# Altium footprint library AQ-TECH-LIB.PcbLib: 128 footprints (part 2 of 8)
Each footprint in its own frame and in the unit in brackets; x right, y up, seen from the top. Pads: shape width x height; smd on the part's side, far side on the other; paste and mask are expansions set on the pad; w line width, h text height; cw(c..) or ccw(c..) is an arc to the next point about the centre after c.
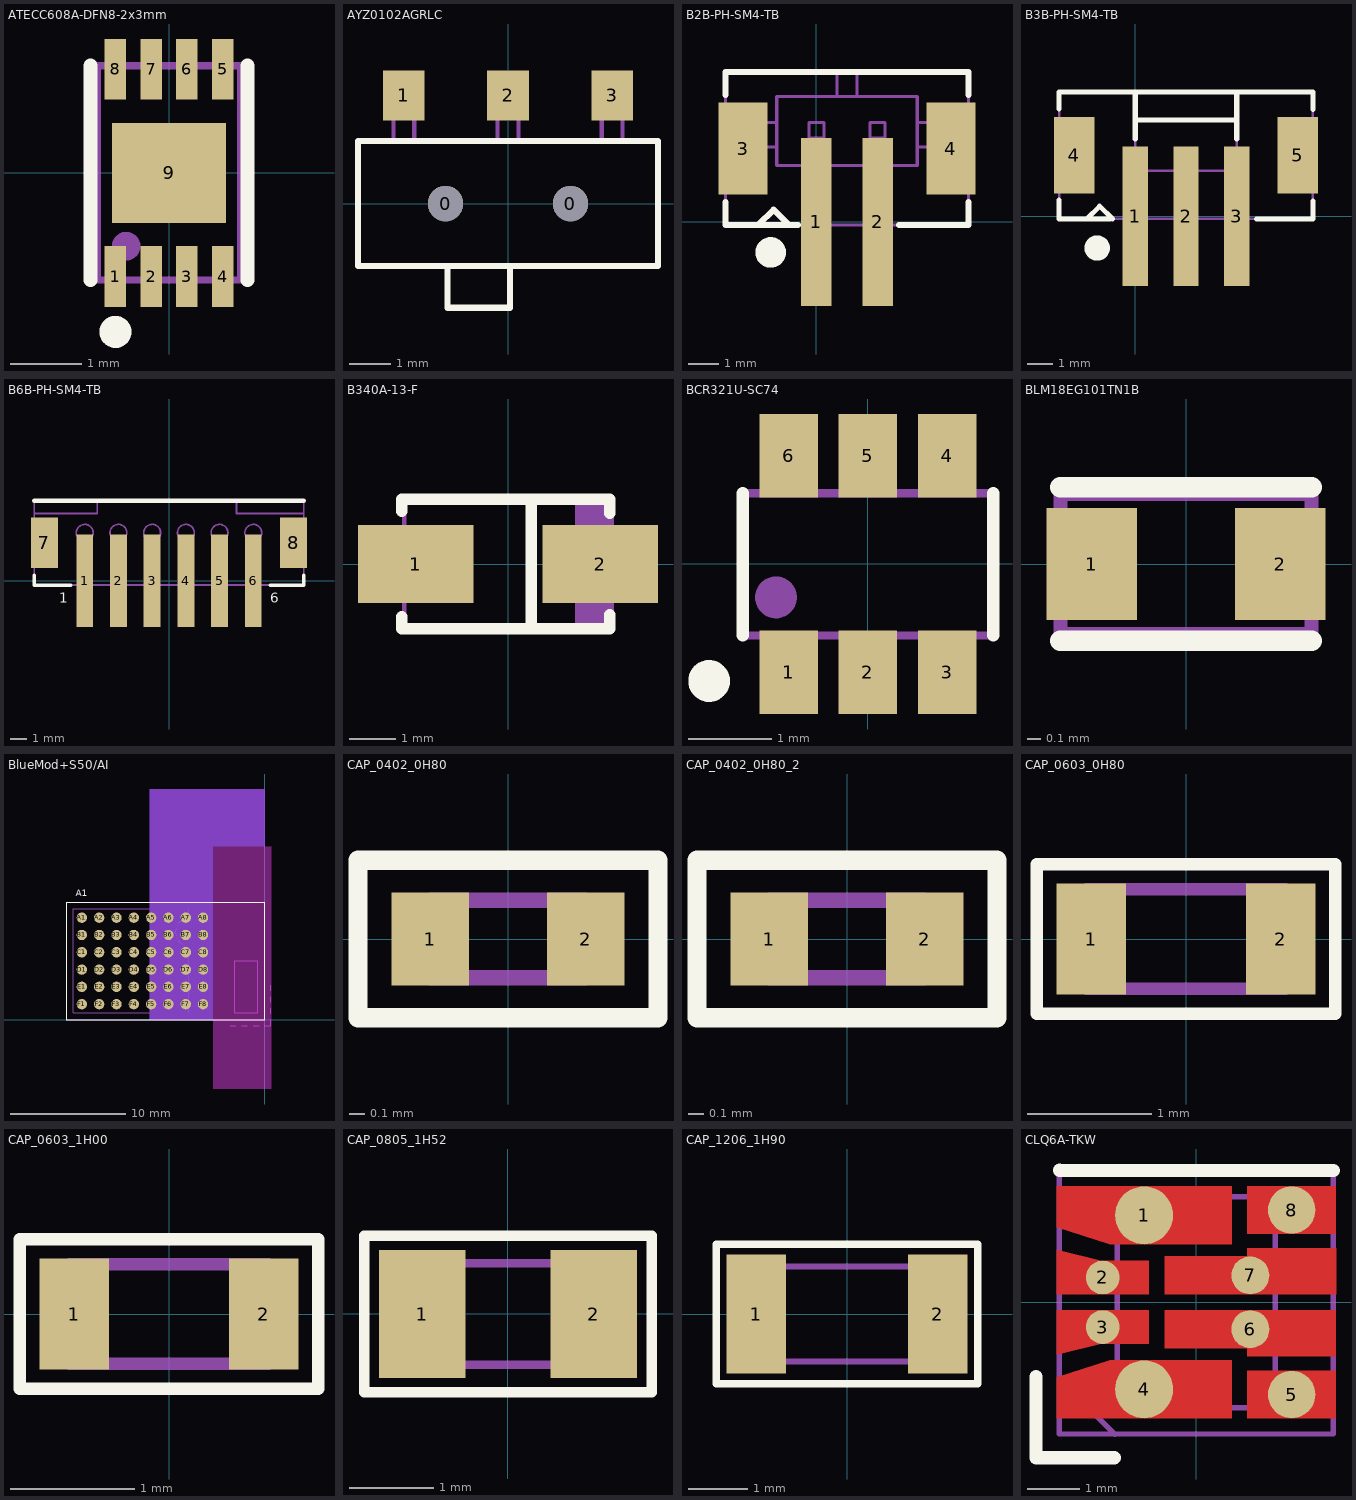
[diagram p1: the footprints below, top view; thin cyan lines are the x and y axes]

## ATECC608A-DFN8-2x3mm [mm]
height 0.6
pads (9):
  rect 0.3x0.85 smd mask+0.05: 1(-0.75,-1.45) 2(-0.25,-1.45) 3(0.25,-1.45) 4(0.75,-1.45) 5(0.75,1.45) 6(0.25,1.45) 7(-0.25,1.45) 8(-0.75,1.45)
  rect 1.6x1.4 smd: 9(0,0)
Top Overlay:
  circle w0.25: c-0.75,-2.225 r0.1
  lines w0.2: -1.1,-1.5 -1.1,1.5 ; 1.1,-1.5 1.1,1.5
Mechanical 3:
  circle w0.2: c-0.6,-1.025 r0.1
  lines w0.1: -1,-1.5 1,-1.5 1,1.5 -1,1.5 -1,-1.5
  text ".Designator" at -1.35,-1.25 h0.84
3D body: height 0.61, standoff 0, extent -0.849,-1.274 -0.351,-0.775
3D body: height 0.6, standoff 0, extent -1,-1.5 1,1.5

## AYZ0102AGRLC [mm]
height 1.5
pads (5):
  round 0.85 hole 0.85 paste+0 mask+0.05: 0(-1.5,0) 0(1.5,0)
  rect 1x1.2 smd paste+0 mask+0.05: 1(-2.5,2.6) 2(0,2.6) 3(2.5,2.6)
Top Overlay:
  lines w0.15: -3.6,-1.5 3.6,-1.5 3.6,1.5 -3.6,1.5 -3.6,-1.5 ; -1.45,-2.5 0.05,-2.5 0.05,-1.5 -1.45,-1.5 -1.45,-2.5
Mechanical 3:
  lines w0.1: -3.6,-1.5 -3.6,1.5 3.6,1.5 3.6,-1.5 -3.6,-1.5 ; -2.75,1.5 -2.75,2.8 -2.25,2.8 -2.25,1.5 -2.75,1.5 ; -1.45,-2.5 0.05,-2.5 0.05,-1.5 -1.45,-1.5 -1.45,-2.5 ; -0.25,1.5 0.25,1.5 0.25,2.8 -0.25,2.8 -0.25,1.5 ; 2.25,1.5 2.75,1.5 2.75,2.8 2.25,2.8 2.25,1.5
  text ".Designator" at -0.04,-0.04 h0.84
3D body: height 0.2, standoff 0, extent 2.25,1.5 2.75,2.8
3D body: height 0.2, standoff 0, extent -0.25,1.5 0.25,2.8
3D body: height 0.2, standoff 0, extent -2.75,1.5 -2.25,2.8
3D body: height 1.3, standoff 0.8, extent -1.45,-2.5 0.05,-1.5
3D body: height 1.5, standoff 0, extent -3.6,-1.5 3.6,1.5

## B2B-PH-SM4-TB [mm]
height 6.6
pads (4):
  rect 1x5.5 smd paste+0 mask+0.1: 1(0,0) 2(2,0)
  rect 1.6x3.02 smd paste+0 mask+0.1: 3(-2.4,2.4) 4(4.4,2.4)
Top Overlay:
  circle w0.5: c-1.5,-1 r0.25
  lines w0.2: -2.975,0.65 -2.975,-0.1 -0.6,-0.1 ; -2.975,4.15 -2.975,4.9 4.975,4.9 4.975,4.15 ; -1.9,-0.1 -1.4,0.4 -0.9,-0.1 ; 2.7,-0.1 4.975,-0.1 4.975,0.65
Mechanical 3:
  lines w0.1: -2.925,1.3 -2.925,3.5 ; -2.325,1.3 -2.325,3.5 ; -1.9,-0.1 -1.4,0.4 -0.9,-0.1 ; -0.25,-0.1 -0.25,-2.1 0.25,-2.1 0.25,-0.1 ; 1.75,-0.1 1.75,-2.1 2.25,-2.1 2.25,-0.1 ; 4.325,1.3 4.325,3.5 4.925,3.5 4.925,1.3 ; -2.075,2.45 -2.075,1.3 -2.975,1.3 -2.975,-0.1 4.975,-0.1 4.975,1.3 4.075,1.3 4.075,2.45 ; -2.075,2.45 -1.3,2.45 ; -2.075,2.45 -2.075,3.25 ; -2.075,3.25 -2.075,3.5 -2.975,3.5 -2.975,4.9 0.675,4.9 ; -2.075,3.25 -1.3,3.25 ; -1.3,2.45 -1.3,1.85 3.3,1.85 3.3,2.45 ; -1.3,2.45 -1.3,3.25 ; -1.3,3.25 -1.3,4.1 0.675,4.1 ; 0.675,4.1 1.325,4.1 ; 0.675,4.1 0.675,4.9 ; 0.675,4.9 1.325,4.9 ; 1.325,4.1 1.325,4.9 ; 1.325,4.1 3.3,4.1 3.3,3.25 ; 1.325,4.9 4.975,4.9 4.975,3.5 4.075,3.5 4.075,3.25 ; 3.3,2.45 4.075,2.45 ; 3.3,2.45 3.3,3.25 ; 3.3,3.25 4.075,3.25 ; 4.075,2.45 4.075,3.25 ; -0.25,2.75 -0.25,3.25 0.25,3.25 0.25,2.75 -0.25,2.75 ; 1.75,2.75 1.75,3.25 2.25,3.25 2.25,2.75 1.75,2.75
  text "2" at 2.5,0.2 h0.84
  text "1" at -0.9,0.3 h0.84
  text ".Designator" at -3.6,1.844 h0.84
3D body "B2B-PH-SM4-TB(LF)(SN)--3DModel-STEP-56544.STEP": height 6.71, standoff -0.04, extent -2.975,-2.1 4.975,4.9

## B3B-PH-SM4-TB [mm]
height 6.6
pads (5):
  rect 1x5.5 smd paste+0 mask+0.1: 1(0,0) 2(2,0) 3(4,0)
  rect 1.6x3.02 smd paste+0 mask+0.1: 4(-2.4,2.4) 5(6.4,2.4)
Top Overlay:
  circle w0.5: c-1.5,-1.25 r0.25
  lines w0.2: -3,0.647 -3,-0.1 -2.6,-0.1 -1.8,-0.1 -1,-0.1 ; -3,4.234 -3,4.9 7,4.9 7,4.205 ; -2,4.9 4,4.9 ; -1.9,-0.1 -1.4,0.4 -0.9,-0.1 ; 0,3.041 0,4.8 ; 0,4.9 0,3.8 4,3.8 4,4.9 ; 4,3.051 4,4.9 ; 4.778,-0.1 7,-0.1 7,0.608
Mechanical 3:
  lines w0.1: -2,4.9 4,4.9 ; -1.9,-0.1 -1.4,0.4 -0.9,-0.1 ; 0,-0.1 0,1.8 4,1.8 4,-0.1 ; 0,-0.1 4,-0.1 ; 0,-0.1 0,4.9 ; 0,-0.1 4,-0.1 ; 0,4.9 0,3.8 4,3.8 4,4.9 ; 0,4.9 4,4.9 ; 4,-0.1 4,4.9 ; -3,-0.1 -3,4.9 7,4.9 7,-0.1 -3,-0.1
  text ".Designator" at -3.9,1.6 h0.84
  text "1" at -0.9,0.2 h0.84
  text "3" at 4.3,0.2 h0.84
3D body "B3B-PH-SM4-TB-LF--SN---3DModel-STEP-56544.STEP": height 6.71, standoff -0.04, extent -2.975,-2.1 6.975,4.9

## B6B-PH-SM4-TB [mm]
height 6.6
pads (8):
  rect 1x5.5 smd paste+0 mask+0.1: 1(-5,0) 2(-3,0) 3(-1,0) 4(1,0) 5(3,0) 6(5,0)
  rect 1.6x3 smd paste+0 mask+0.1: 7(-7.4,2.25) 8(7.4,2.25)
Top Overlay:
  lines w0.2: -8,0.35 -8,-0.25 -5.825,-0.25 ; 6,-0.25 8,-0.25 8,0.35
  lines w0.25: -8,4.75 8,4.75
  text "6" at 6,-1.5 h1
  text "1" at -6.5,-1.5 h1
Mechanical 3:
  circle w0.1: c5,2.85 r0.5
  circle w0.1: c3,2.85 r0.5
  circle w0.1: c1,2.85 r0.5
  circle w0.1: c-1,2.85 r0.5
  circle w0.1: c-3,2.85 r0.5
  circle w0.1: c-5,2.85 r0.5
  lines w0.1: -8,4 -4.25,4 -4.25,4.75 ; 4,4.75 4,4 8,4 ; -8,-0.25 -8,4.75 8,4.75 8,-0.25 -8,-0.25
  text "6" at 5,0.25 h1
  text "1" at -5,0.25 h1
  text ".Designator" at 0,0.5 h0.84
3D body "B6B-PH-SM4-TB(LF)(SN)--3DModel-STEP-56544.STEP": height 6.75, standoff 0, extent -7.975,-2.25 7.975,4.75

## B340A-13-F [mm]
height 2.4
pads (2):
  rect 2.5x1.7 smd paste+0 mask+0.1: 1(-2,0) 2(2,0)
Top Overlay:
  lines w0.25: -2.3,-1.143 -2.3,-1.4 2.2,-1.4 2.2,-1.1 ; -2.3,1.143 -2.3,1.4 2.2,1.4 2.2,1.1 ; 0.5,-1.3 0.5,1.4
Mechanical 3:
  region: 1.5,-1.39 2.24,-1.39 2.24,1.4 1.5,1.4
  lines w0.1: 1.5,-1.395 1.5,1.395 ; -2.64,-0.735 -2.64,0.735 -2.25,0.735 -2.25,-0.735 -2.64,-0.735 ; -2.25,-1.395 -2.25,1.395 2.25,1.395 2.25,-1.395 -2.25,-1.395 ; 2.25,-0.735 2.64,-0.735 2.64,0.735 2.25,0.735 2.25,-0.735
  text ".Designator" at -2,0 h0.84
3D body "DO214AC(refusion).stp": height 2.4, standoff 0, extent -2.6,-1.3 2.6,1.3

## BCR321U-SC74 [mm]
height 1.1
pads (6):
  rect 0.7x1 smd paste+0 mask+0.05: 1(-0.95,-1.295) 2(0,-1.295) 3(0.95,-1.295) 4(0.95,1.295) 5(0,1.295) 6(-0.95,1.295)
Top Overlay:
  circle w0.3: c-1.9,-1.4 r0.1
  lines w0.15: -1.5,-0.855 -1.5,0.845 ; 1.5,-0.855 1.5,0.845
Mechanical 3:
  circle w0.3: c-1.1,-0.4 r0.1
  lines w0.1: -1.5,-0.855 -1.5,0.845 1.5,0.845 1.5,-0.855 -1.5,-0.855
  text ".Designator" at 1.25,0.525 h1
3D body: height 1.1, standoff 0, extent -1.5,-0.855 1.5,0.845
3D body: height 1.11, standoff 0, extent -1.349,-0.65 -0.851,-0.15

## BLM18EG101TN1B [mm]
height 0.65
pads (2):
  rect 0.65x0.8 smd: 1(-0.675,0) 2(0.675,0)
Top Overlay:
  lines w0.15: -0.9,-0.55 0.9,-0.55 ; -0.9,0.55 0.9,0.55
Mechanical 3:
  lines w0.1: -0.9,-0.5 -0.9,0.5 0.9,0.5 0.9,-0.5 -0.9,-0.5
  text "'.Designator'" at 0,0 h1
3D body: height 0.65, standoff 0, extent -0.9,-0.5 0.9,0.5

## BlueMod+S50/AI [mm]
height 3.05
pads (48):
  round 0.9 smd: A1(-15.85,8.85) A2(-14.35,8.85) A3(-12.85,8.85) A4(-11.35,8.85) A5(-9.85,8.85) A6(-8.35,8.85) A7(-6.85,8.85) A8(-5.35,8.85) B1(-15.85,7.35) B2(-14.35,7.35) B3(-12.85,7.35) B4(-11.35,7.35) B5(-9.85,7.35) B6(-8.35,7.35) B7(-6.85,7.35) B8(-5.35,7.35) C1(-15.85,5.85) C2(-14.35,5.85) C3(-12.85,5.85) C4(-11.35,5.85) C5(-9.85,5.85) C6(-8.35,5.85) C7(-6.85,5.85) C8(-5.35,5.85) D1(-15.85,4.35) D2(-14.35,4.35) D3(-12.85,4.35) D4(-11.35,4.35) D5(-9.85,4.35) D6(-8.35,4.35) D7(-6.85,4.35) D8(-5.35,4.35) E1(-15.85,2.85) E2(-14.35,2.85) E3(-12.85,2.85) E4(-11.35,2.85) E5(-9.85,2.85) E6(-8.35,2.85) E7(-6.85,2.85) E8(-5.35,2.85) F1(-15.85,1.35) F2(-14.35,1.35) F3(-12.85,1.35) F4(-11.35,1.35) F5(-9.85,1.35) F6(-8.35,1.35) F7(-6.85,1.35) F8(-5.35,1.35)
Top Layer keep-out:
  rectangle: -10,10 -4.5,15
  rectangle: -10,15 0,20
Bottom Layer keep-out:
  rectangle: -10,0 -4.5,20
  rectangle: -10,15 0,20
Top Overlay:
  lines w0.1: -17.2,0 0,0 0,10.2 -17.2,10.2 -17.2,0
  text "A1" at -16.4,10.5 h1
Keep-Out Layer:
  rectangle: -4.5,0 0,15
  rectangle: -4.5,-6 0.6,15
Mechanical 3:
  lines w0.1: -3,-0.5 -2.5,-0.5 ; -2,-0.5 -1.5,-0.5 ; -1,-0.5 -0.5,-0.5 ; 0,-0.5 0.5,-0.5 0.5,0 ; 0.5,0.5 0.5,1 ; 0.5,1.5 0.5,2 ; 0.5,2.5 0.5,3 ; -17.2,0 -17.2,10.2 0,10.2 0,0 -17.2,0 ; -16.6,0.6 -6.6,0.6 -6.6,6.4 cw(c-6.6,7.5) -7.7,7.5 -7.7,7.7 cw(c-6.6,7.7) -6.6,8.8 -6.6,9.6 -16.6,9.6 -16.6,0.6 ; -2.6,0.6 -0.6,0.6 -0.6,5.1 -2.6,5.1 -2.6,0.6
  text "'.Designator'" at -10.61,5.261 h1
  text "A1" at -15.355,9.355 h1
3D body: height 1, standoff 0, extent -17.2,0 0,10.2
3D body: height 2.85, standoff 0, extent -16.6,0.6 -6.6,9.6
3D body: height 3.05, standoff 0, extent -2.6,0.6 -0.6,5.1

## CAP_0402_0H80 [mm]
height 0.8
pads (2):
  rect 0.5x0.6 smd: 1(-0.5,0) 2(0.5,0)
Top Overlay:
  lines w0.125: -0.965,-0.508 0.965,-0.508 0.965,0.508 -0.965,0.508 -0.965,-0.508
Mechanical 3:
  lines w0.1: -0.5,-0.25 0.5,-0.25 0.5,0.25 -0.5,0.25 -0.5,-0.25
  text "'.Designator'" at -3.225,-0.35 h0.8
3D body: height 0.8, standoff 0, extent -0.5,-0.25 0.5,0.25

## CAP_0402_0H80_2 [mm]
pads (2):
  rect 0.5x0.6 smd: 1(-0.5,0) 2(0.5,0)
Top Overlay:
  lines w0.125: -0.965,-0.508 0.965,-0.508 0.965,0.508 -0.965,0.508 -0.965,-0.508
Mechanical 3:
  lines w0.1: -0.5,-0.25 -0.5,0.25 0.5,0.25 0.5,-0.25 -0.5,-0.25
  text "'.Designator'" at -0.95,0.15 h0.6
3D body: height 0.8, standoff 0, extent -0.5,-0.25 0.5,0.25

## CAP_0603_0H80 [mil] "refusion"
height 31.5
pads (2):
  rect 22x35 smd: 1(-30,0) 2(30,0)
Top Overlay:
  lines w3.94: -47.24,-23.62 -47.24,23.62 47.24,23.62 47.24,-23.62 -47.24,-23.62
Mechanical 3:
  lines w3.94: -31.5,-15.75 31.5,-15.75 31.5,15.75 -31.5,15.75 -31.5,-15.75
  text "'.Designator'" at 112.2,9.84 h23.62
3D body: height 31.5, standoff 0, extent -31.5,-15.75 31.5,15.75

## CAP_0603_1H00 [mil] "refusion"
height 39.37
pads (2):
  rect 22x35 smd: 1(-30,0) 2(30,0)
Top Overlay:
  lines w3.94: -47.24,-23.62 47.24,-23.62 47.24,23.62 -47.24,23.62 -47.24,-23.62
Mechanical 3:
  lines w3.94: -31.5,-15.75 31.5,-15.75 31.5,15.75 -31.5,15.75 -31.5,-15.75
  text "'.Designator'" at -147.64,-19.68 h31.5
3D body: height 39.37, standoff 0, extent -31.5,-15.75 31.5,15.75

## CAP_0805_1H52 [mm] "refusion"
height 1.52
pads (2):
  rect 1.02x1.52 smd paste+0 mask+0.1: 1(-1.016,0) 2(1.016,0)
Top Overlay:
  lines w0.125: -1.7,-0.925 -1.7,0.925 1.7,0.925 1.7,-0.925 -1.7,-0.925
Mechanical 3:
  lines w0.1: -1,-0.6 -1,0.6 1,0.6 1,-0.6 -1,-0.6
  text "'.Designator'" at -3.627,-0.173 h0.8
3D body: height 1.52, standoff 0, extent -1.638,-0.863 1.638,0.863

## CAP_1206_1H90 [mm] "refusion"
height 1.9
pads (2):
  rect 1x2 smd paste+0 mask+0.1: 1(-1.524,0) 2(1.524,0)
Top Overlay:
  lines w0.125: -2.2,-1.175 -2.2,1.175 2.2,1.175 2.2,-1.175 -2.2,-1.175
Mechanical 3:
  lines w0.1: -1.6,-0.8 -1.6,0.8 1.6,0.8 1.6,-0.8 -1.6,-0.8
  text "'.Designator'" at 1.3,0.425 h0.8
3D body: height 1.9, standoff 0, extent -1.6,-0.8 1.6,0.8

## CLQ6A-TKW [mm]
height 1.2
pads (8):
  round 1.1 smd paste+0 mask+0.05: 1(-0.99,1.65) 4(-0.99,-1.65)
  round 0.64 smd paste+0 mask+0.1: 2(-1.775,0.47) 3(-1.775,-0.47)
  round 0.9 smd paste+0 mask+0.1: 5(1.81,-1.75) 8(1.81,1.75)
  round 0.72 smd mask+0.05: 6(1.025,-0.51) 7(1.025,0.51)
Top Layer:
  region: 0.97,-1.3 2.65,-1.3 2.65,-2.2 0.97,-2.2
  region: -0.9,0.15 -0.9,0.79 -1.8,0.79 -2.65,1 -2.65,0.15
  region: -0.9,-0.15 -0.9,-0.79 -1.8,-0.79 -2.65,-1 -2.65,-0.15
  region: -0.6,-0.15 2.65,-0.15 2.65,-1.02 0.97,-1.02 0.97,-0.87 -0.6,-0.87
  region: -0.6,0.15 2.65,0.15 2.65,1.02 0.97,1.02 0.97,0.87 -0.6,0.87
  region: 0.97,2.2 2.65,2.2 2.65,1.3 0.97,1.3
  region: -0.99,2.2 0.67,2.2 0.67,1.1 -1.64,1.1 -2.65,1.42 -2.65,2.2
  region: -0.99,-2.2 0.67,-2.2 0.67,-1.1 -1.64,-1.1 -2.65,-1.42 -2.65,-2.2
Top Overlay:
  lines w0.25: -3.04,-1.41 -3.04,-1.743 -3.04,-2.407 -3.04,-2.95 -1.555,-2.95 ; -2.595,2.505 2.6,2.5
Mechanical 3:
  lines w0.1: -2.595,-1.46 -1.545,-2.51 ; -1.5,1.5 cw(c-1,1.5) -1,2 1,2 cw(c1,1.5) 1.5,1.5 1.5,-1.5 cw(c1,-1.5) 1,-2 -1,-2 cw(c-1,-1.5) -1.5,-1.5 -1.5,1.5 ; -1.5,1.5 -1.5,1.5 ; -2.6,-2.5 2.6,-2.5 2.6,2.5 -2.6,2.5 -2.6,-2.5
  text "'.Designator'" at -0.9,-0.15 h1
3D body: height 1.2, standoff 0, extent -2.6,-2.5 2.6,2.5
3D body: height 1.21, standoff 0, extent -2.6,-2.51 -1.545,-1.46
